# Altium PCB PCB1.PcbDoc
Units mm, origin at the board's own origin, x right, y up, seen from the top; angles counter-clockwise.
Board outline 106 x 54 mm, 2 copper layers (Top Layer, Bottom Layer), stack 1.571 mm thick; 62 components, 67 nets, 276 pads, 44 vias.
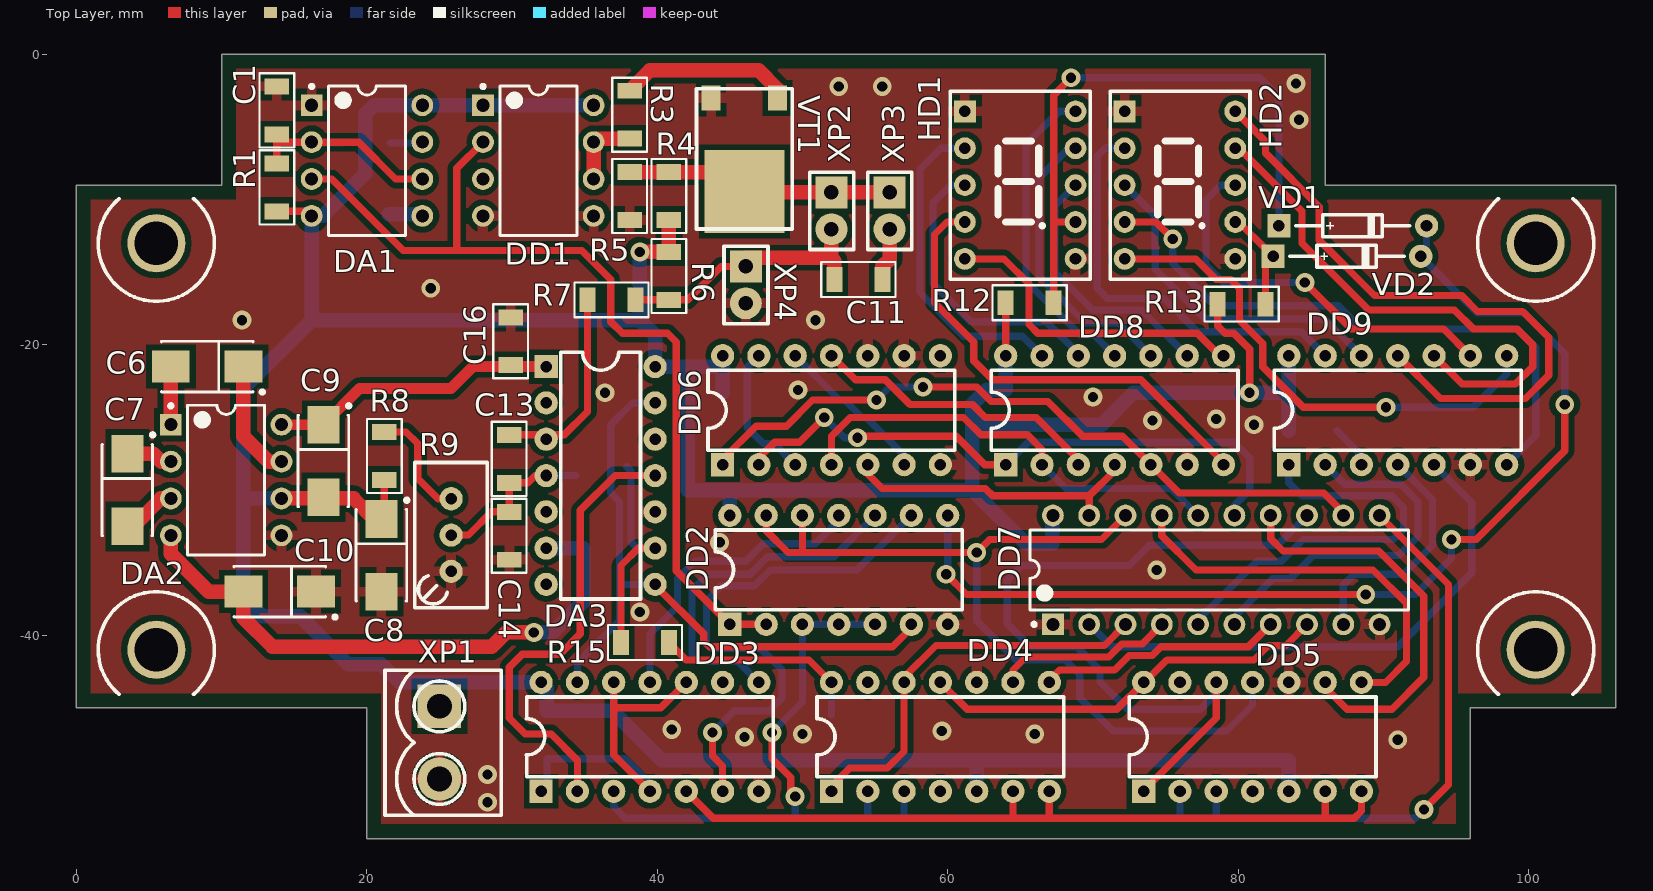
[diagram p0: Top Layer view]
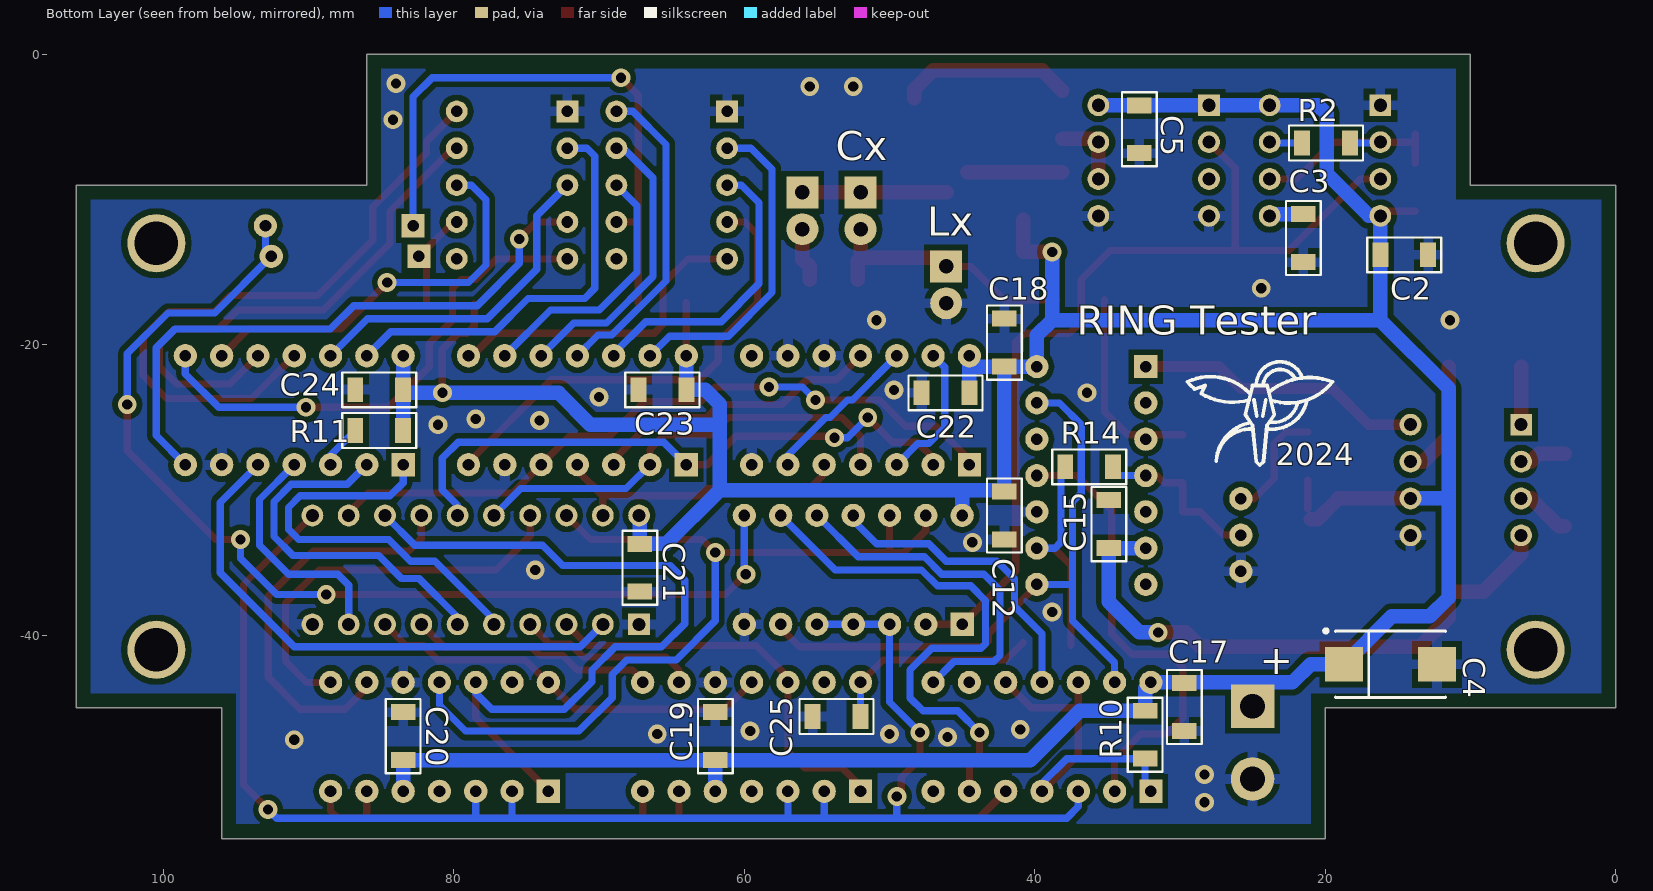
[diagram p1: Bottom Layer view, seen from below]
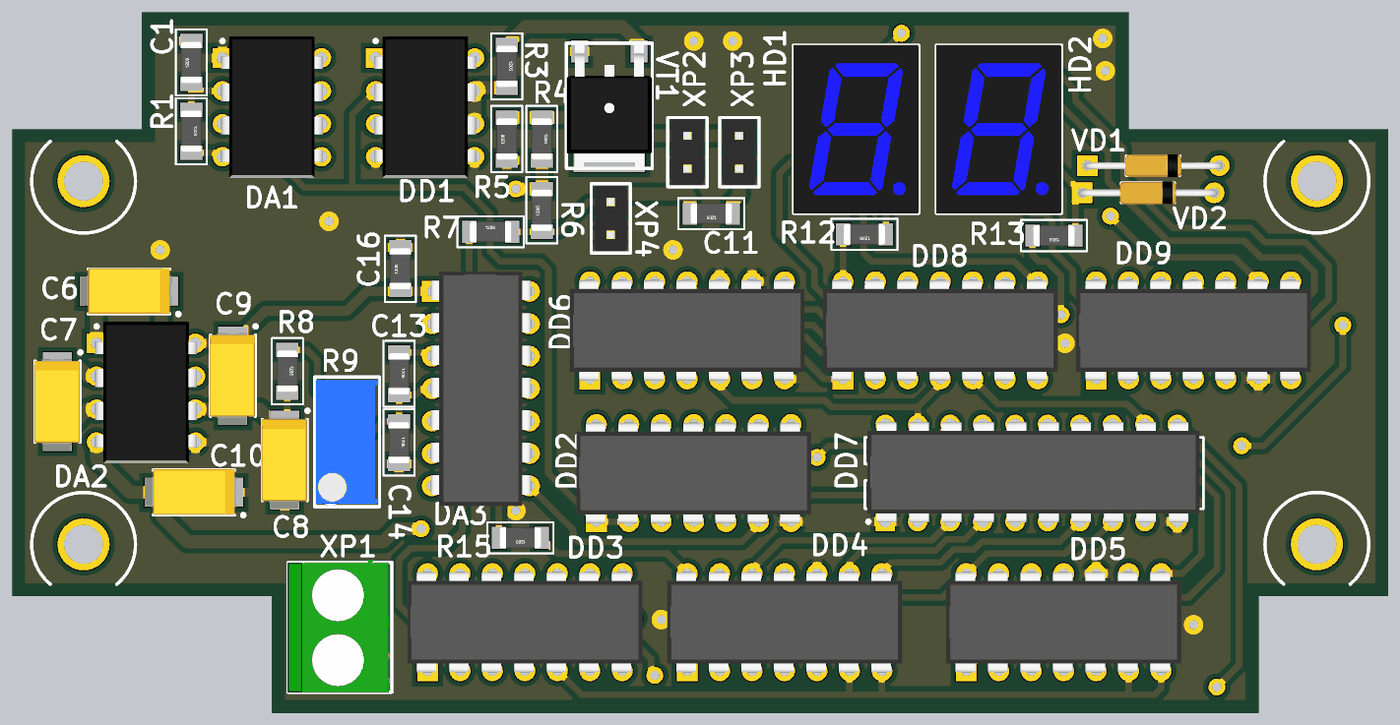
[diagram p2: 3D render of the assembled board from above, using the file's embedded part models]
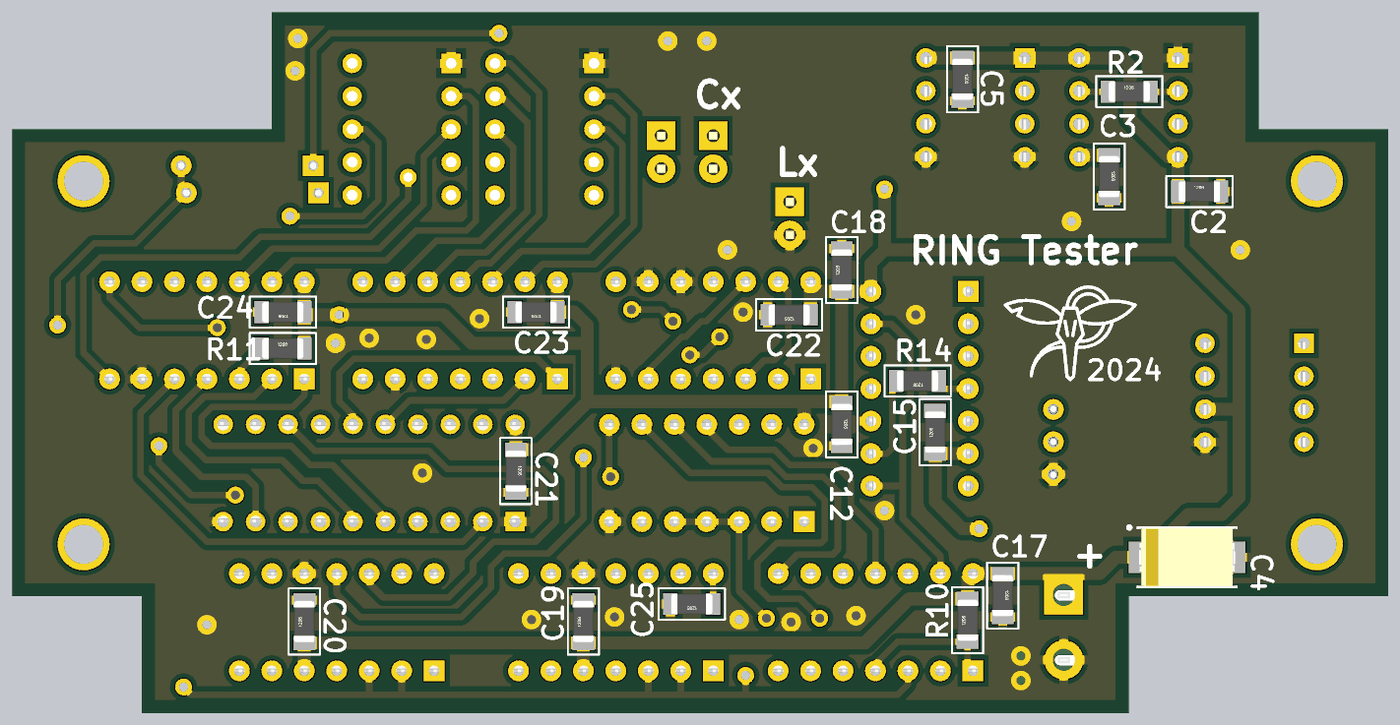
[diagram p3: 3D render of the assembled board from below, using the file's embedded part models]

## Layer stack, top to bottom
Top Layer: signal copper 0.0356
Dielectric: core 1.5, FR-4, Dk 4.8
Bottom Layer: signal copper 0.0356

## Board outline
0,-45 0,-9 10,-9 10,0 86,0 86,-9 106,-9 106,-45 96,-45 96,-54 20,-54 20,-45

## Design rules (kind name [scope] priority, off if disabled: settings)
Clearance Clearance_poly [InPolygon] p1: gap=0.4
Clearance [All] p2: gap=0.2
ComponentClearance [All] p1: gap=0.25 collisioncheckmode=3 verticalgap=0.25 showdistances=FALSE
Height [All] p1: minheight=0 maxheight=45 prefheight=12.7
PolygonConnect [All] p1: connectstyle=Relief reliefconductorwidth=0.7 reliefentries=4 polygonreliefangle="90 Angle"
RoomDefinition Sch1 [InComponentClass('Sch1')] p1: confinementstyle=ConfineIn formatcopy=TRUE lockcomponents=FALSE outline 0,-54 106,-54 106,0 0,0
RoutingVias [All] p1: holewidth=0.7 width=1.3 viastyle="Through Hole" minholewidth=0.5 minwidth=1 maxholewidth=1 maxwidth=1.5
SilkscreenOverComponentPads [All] p1: minsilkscreentomaskgap=0.254
SolderMaskExpansion [All] p1: expansion=0.102
Width [All] p1: maxlimit=5 minlimit=0.3 preferedwidth=0.7
25 further rules are at their usual default settings.

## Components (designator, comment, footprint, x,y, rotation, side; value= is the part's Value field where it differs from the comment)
2024 "2024" "Rat's logo" 24.5,-24.8 r180 bottom
C1 "C_1206" RC_1206 13.8,-5.5 r90 top
C2 "C_1206" RC_1206 16.2,-13.8 r180 bottom
C3 "C_1206" RC_1206 21.5,-11 r270 bottom
C4 "Type D" "Type D" 15.5,-42 r180 bottom
C5 "C_1206" RC_1206 32.8,-3.5 r270 bottom
C6 "Type C" "Type C" 9,-21.5 r180 top
C7 "Type C" "Type C" 3.5,-30 r270 top
C8 "Type C" "Type C" 21,-34.5 r270 top
C9 "Type C" "Type C" 17,-28 r270 top
C10 "Type C" "Type C" 14,-37 r180 top
C11 "C_1206" RC_1206 55.5,-15.5 r180 top
C12 "C_1206" RC_1206 42.1,-30.1 r270 bottom
C13 "C_1206" RC_1206 29.8,-26.2 r270 top
C14 "C_1206" RC_1206 29.8,-31.5 r270 top
C15 "C_1206" RC_1206 34.9,-34 r90 bottom
C16 "C_1206" RC_1206 29.9,-21.4 r90 top
C17 "C_1206" RC_1206 29.7,-43.3 r270 bottom
C18 "C_1206" RC_1206 42.1,-21.5 r90 bottom
C19 "C_1206" RC_1206 62,-48.6 r90 bottom
C20 "C_1206" RC_1206 83.5,-48.6 r90 bottom
C21 "C_1206" RC_1206 67.2,-33.7 r270 bottom
C22 "C_1206" RC_1206 44.5,-23.3 r0 bottom
C23 "C_1206" RC_1206 64,-23.1 r0 bottom
C24 "C_1206" RC_1206 83.5,-23.1 r0 bottom
C25 "C_1206" RC_1206 52,-45.6 r0 bottom
DA1 "NE555" DIP-8 16.2,-3.5 r0 top
DA2 "MAX680" DIP-8 6.5,-25.5 r0 top
DA3 "К554СА4" DIP-14-RU 36.1,-29 r0 top
DD1 "TC4420" DIP-8 28,-3.5 r0 top
DD2 "К1533ЛА3" DIP-14-RU 52.5,-35.5 r90 top
DD3 "КР1533ТМ2" DIP-14-RU 39.5,-47 r90 top
DD4 "КР1533ИЕ2" DIP-14-RU 59.5,-47 r90 top
DD5 "КР1533ИЕ2" DIP-14-RU 81,-47 r90 top
DD6 "К1533ЛЛ1" DIP-14-RU 52,-24.5 r90 top
DD7 "КР1533ИР23" DIP-20-RU 78.5,-35.5 r90 top
DD8 "КР514ИД1" DIP-14-RU 71.5,-24.5 r90 top
DD9 "КР514ИД1" DIP-14-RU 91,-24.5 r90 top
HD1 "HDSP-F513" HDSP-F 65,-9 r0 top
HD2 "HDSP-F513" HDSP-F 76,-9 r0 top
R1 "R_1206" RC_1206 13.8,-7.5 r270 top
R2 "R_1206" RC_1206 21.6,-6.1 r180 bottom
R3 "R_1206" RC_1206 38.1,-2.5 r270 top
R4 "R_1206" RC_1206 40.8,-8.1 r270 top
R5 "R_1206" RC_1206 38.1,-11.4 r90 top
R6 "R_1206" RC_1206 40.8,-16.9 r90 top
R7 "R_1206" RC_1206 35.2,-16.9 r0 top
R8 "R_1206" RC_1206 21.2,-26 r270 top
R9 "3296" 3296W 25.8,-35.6 r90 top
R10 "R_1206" RC_1206 32.4,-48.5 r90 bottom
R11 "R_1206" RC_1206 86.8,-25.9 r180 bottom
R12 "R_1206" RC_1206 67.3,-17.1 r180 top
R13 "R_1206" RC_1206 81.9,-17.2 r180 top
R14 "R_1206" RC_1206 34.6,-28.4 r0 bottom
R15 "R_1206" RC_1206 40.8,-40.5 r180 top
VD1 "КД522" DO-35 87.9,-11.8 r0 top
VD2 "КД522" DO-35 87.5,-13.9 r0 top
VT1 "30N03A" TO-252 46,-3 r180 top
XP1 "Power" 2EDGV-2P 25,-44.9 r270 top
XP2 "Cap" PLS-2 52,-9.5 r270 top
XP3 "Sw" PLS-2 56,-9.5 r270 top
XP4 "Ind" PLS-2 46.1,-14.6 r270 top

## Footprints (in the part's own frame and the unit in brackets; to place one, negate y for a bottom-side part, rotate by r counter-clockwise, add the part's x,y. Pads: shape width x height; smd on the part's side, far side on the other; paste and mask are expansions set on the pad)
2EDGV-2P [mm]
  rect 3x3 hole 1.7: 1(0,0)
  round 3 hole 1.7: 2(5,0)
  silkscreen extent -2.5,-3.75 7.5,4.25, body extent -2.72,-3.8 7.52,4, height 10.22
3296W [mm]
  round 1.6 hole 0.8: 1(0,0) 2(2.5,0) 3(5,0)
  silkscreen extent -2.5,-2.5 7.5,2.5, body extent -2.26,-2.42 7.27,2.41, height 11.55
DIP-8 [mm] "DIP; 8 Leads; Row Spacing 7.62 mm; Pitch 2.54 mm"
  rect 1.5x1.5 hole 0.9: 1(0,0)
  round 1.5 hole 0.9: 2(0,-2.54) 3(0,-5.08) 4(0,-7.62) 5(7.62,-7.62) 6(7.62,-5.08) 7(7.62,-2.54) 8(7.62,0)
  silkscreen extent -0.12,-8.96 6.46,1.42, body extent -0.12,-9.27 7.75,1.65, height 5.08
DIP-14-RU [mm]
  rect 1.6x1.6 hole 0.8: 1(-3.75,7.5)
  round 1.6 hole 0.8: 2(-3.75,5) 3(-3.75,2.5) 4(-3.75,0) 5(-3.75,-2.5) 6(-3.75,-5) 7(-3.75,-7.5) 8(3.75,-7.5) 9(3.75,-5) 10(3.75,-2.5) 11(3.75,0) 12(3.75,2.5) 13(3.75,5) 14(3.75,7.5)
  silkscreen extent -2.75,-8.5 2.75,8.5, body extent -3.88,-9.05 3.88,9.05, height 4.5
DIP-20-RU [mm]
  rect 1.5x1.5 hole 0.9: 1(-3.75,11.25)
  round 1.5 hole 0.9: 2(-3.75,8.75) 3(-3.75,6.25) 4(-3.75,3.75) 5(-3.75,1.25) 6(-3.75,-1.25) 7(-3.75,-3.75) 8(-3.75,-6.25) 9(-3.75,-8.75) 10(-3.75,-11.25) 11(3.75,-11.25) 12(3.75,-8.75) 13(3.75,-6.25) 14(3.75,-3.75) 15(3.75,-1.25) 16(3.75,1.25) 17(3.75,3.75) 18(3.75,6.25) 19(3.75,8.75) 20(3.75,11.25)
  silkscreen extent -3.87,-13.25 2.75,12.82, body extent -3.82,-12.98 3.94,12.62, height 4.5
DO-35 [mm]
  rect 1.6x1.6 hole 0.8: 1(-5.084,0)
  round 1.6 hole 0.8: 2(5.084,0)
  silkscreen extent -3.94,-0.75 3.94,0.75, body extent -5.35,-0.89 5.34,0.86, height 2.15
HDSP-F [mm]
  rect 1.5x1.5 hole 0.8: 1(-3.81,5.08)
  round 1.5 hole 0.8: 2(-3.81,2.54) 3(-3.81,0) 4(-3.81,-2.54) 5(-3.81,-5.08) 6(3.81,-5.08) 7(3.81,-2.54) 8(3.81,0) 9(3.81,2.54) 10(3.81,5.08)
  silkscreen extent -4.81,-6.48 4.83,6.48, body extent -4.8,-6.5 4.8,6.5, height 7
PLS-2 [mm]
  rect 2.2x2.2 hole 1: 1(0,0)
  round 2.2 hole 1: 2(2.54,0)
  silkscreen extent -1.4,-1.5 3.94,1.52, body extent -1.27,-1.27 3.81,1.27, height 8.54
"Rat's logo" [mm]
  silkscreen extent -5,-3.5 5,3.64
RC_1206 [mm]
  rect 1.1x1.7 smd: 1(0,0) 2(3.3,0)
  silkscreen extent -0.9,-1.2 4.2,1.2, body extent 0.05,-0.8 3.25,0.8, height 1
TO-252 [mm]
  rect 1.3x1.7 smd: 1(-2.285,0) 3(2.285,0)
  rect 5.5x5.7 smd: 2(0,6.44)
  silkscreen extent -3.3,-0.64 3.3,9.02, body extent -3.29,-0.65 3.29,9.05, height 2.3
"Type C" [mm]
  rect 2.6x2.2 smd: 1(-2.5,0) 2(2.5,0)
  silkscreen extent -3.93,-1.75 3.15,1.87, body extent -3.8,-1.8 3.8,1.71, height 2.79
"Type D" [mm]
  rect 2.6x2.4 smd: 1(-3.2,0) 2(3.2,0)
  silkscreen extent -4.58,-2.3 3.8,2.42, body extent -3.7,-2.22 3.7,2.23, height 3

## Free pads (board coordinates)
  round 4 hole 3: 0(5.5,-41) 0(5.5,-13) 0(100.5,-41) 0(100.5,-13)

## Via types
v1: diameter 1.3, hole 0.7, Top Layer to Bottom Layer, 44 vias

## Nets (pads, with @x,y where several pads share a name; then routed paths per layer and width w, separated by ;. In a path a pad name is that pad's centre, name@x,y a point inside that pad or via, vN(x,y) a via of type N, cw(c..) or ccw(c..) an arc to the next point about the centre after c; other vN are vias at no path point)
GND: C1.2 C2.2 C3.2 C4.2 C5.2 C8.2 C10.1 C12.2 C14.2 C15.2 C16.2 C17.2 C18.2 C19.2 C20.2 C21.2 C22.2 C23.2 C24.2 C25.2 DA1.1 DA2.5 DA3.10 DD1.4 DD1.5 DD2.7 DD3.7 DD4.10 DD5.10 DD6.7 DD6.9 DD6.10 DD7.1 DD7.10 DD8.6 DD9.6 HD1.1 HD1.6 HD2.1 HD2.6 R5.1 R9.1 VT1.3 XP1.2 XP4.2
  other v1: 28.3,-51.5 28.3,-49.6 91,-47.2 46,-47 50,-46.8 66,-46.8 59.6,-46.6 41,-46.5 38.8,-38.4 74.4,-35.5 44.3,-33.6 81.1,-25.5 74.1,-25.2 78.5,-25.1 70,-23.6 36.4,-23.3 49.7,-23.1 11.4,-18.3 50.9,-18.3 24.4,-16.1 84.2,-4.5 52.5,-2.2 55.5,-2.2 84,-2
NetC1_1: C1.1 DA1.2 DA1.6 R1.1 R2.2 | length 15.1
  Top Layer w0.5: R1.1 C1.1 ; C1.1@13.86,-6.04 DA1.2 19.44,-6.04 21.98,-8.58 DA1.6
  Bottom Layer w0.5: DA1.2@16.26,-6.1 R2.2
NetC3_1: C3.1 DA1.5 | length 2.2
  Bottom Layer w1: C3.1 DA1.5@23.7,-11
NetC6_1: C6.1 DA2.7 | length 8.1
  Top Layer w1: C6.1 11.5,-26.3 13.24,-28.04 DA2.7
NetC6_2: C6.2 DA2.1 | length 4
  Top Layer w1: DA2.1 C6.2
NetC7_1: C7.1 DA2.2 | length 3.2
  Top Layer w1: C7.1 5.3,-27.5 5.84,-28.04 DA2.2
NetC7_2: C7.2 DA2.3 | length 3.8
  Top Layer w1: C7.2 3.9,-32.5 5.82,-30.58 DA2.3
NetC11_1: C11.1 XP3.2 | length 3.7
  Top Layer w1: C11.1 55.5,-14.6 56,-14.1 XP3.2
NetC11_2: C11.2 R6.1 R7.2 XP2.2 XP4.1 | length 18
  Top Layer w0.5: R7.2 R6.1 42.1,-16.9 44.4,-14.6 XP4.1
  Top Layer w1: XP4.1@46.1,-14 52,-14 ; XP2.2 52,-14 ; C11.2 52.2,-14.2 52,-14
NetC13_1: C13.1 DA3.3 R7.1 | length 13.8
  Top Layer w0.5: C13.1 33.6,-26.2 35.2,-24.6 R7.1
NetC13_2: C13.2 C14.1 DA3.4 R9.2 R14.1 | length 11.5
  Top Layer w0.5: R9.2 27,-33.1 28.6,-31.5 C14.1 C13.2 31.1,-29.5 31.6,-29 DA3.4
  Bottom Layer w0.5: DA3.4 R14.1@34.4,-29
NetC25_1: C25.1 DD4.14 R15.1 | length 14.6
  Top Layer w0.5: R15.1 42,-41.7 50.45,-41.7 DD4.14
  Bottom Layer w0.5: C25.1@52,-45.5 DD4.14
NetDA1_3: DA1.3 DD1.2 DD2.1 DD2.2 | length 63.1
  Top Layer w0.5: DA1.3 17.58,-8.58 22.5,-13.5 26.2,-13.5 ; DD1.2 26.2,-7.84 26.2,-13.5 ; DD2.2 DD2.1 41.3,-35.55 41.3,-19.8 40.7,-19.2 37.6,-19.2 36.8,-18.4 36.8,-15.5 34.8,-13.5 26.2,-13.5
NetDA1_7: DA1.7 R2.1 | length 2.2
  Bottom Layer w0.5: R2.1 DA1.7@23.76,-6.1
NetDA3_8: DA3.8 DA3.13 DD2.6 DD3.13 | length 45.8
  Top Layer w0.5: DA3.8 39.85,-36.55 43.2,-39.9 43.2,-40.4 43.6,-40.8 56.2,-40.8 57.5,-39.5 DD2.6
  Bottom Layer w0.5: DD3.13 34.5,-41.9 37.4,-39 37.4,-36.6 ; DA3.8 37.4,-36.5 37.4,-30.8 36.8,-30.2 36.8,-25.5 38.3,-24 DA3.13
NetDA3_9: DA3.9 R14.2 R15.2 | length 15.5
  Top Layer w0.5: R15.2@37.5,-40.7 37.5,-35.2 38.7,-34 DA3.9
  Bottom Layer w0.5: R14.2 38.2,-28.7 38.2,-33.6 38.6,-34 DA3.9
NetDA3_11: DA3.11 DD3.2 | length 32
  Top Layer w0.5: DD3.2 34.5,-48.6 32.7,-46.8 30.9,-46.8 29.8,-45.7 29.8,-42.2 30.7,-41.3 33.3,-41.3 34.7,-39.9 34.7,-31.4 37.1,-29 DA3.11
NetDD1_6: DD1.6 DD1.7 R3.2 | length 5.1
  Top Layer w1: DD1.6 DD1.7 35.86,-5.8 R3.2
NetDD2_3: DD2.3 DD2.4 DD2.5 DD3.3 DD4.2 DD4.3 DD5.2 DD5.3 DD7.11 | length 107.5
  Top Layer w0.5: v1(47.9,-46.7) 47.9,-48.5 49.2,-49.8 49.2,-50.8 v1(49.5,-51.1) ; DD7.11 94.5,-36.5 94.5,-50.3 v1(92.8,-52)
  Bottom Layer w0.5: DD3.3 37,-51.8 37.8,-52.6 49.5,-52.6 ; v1(47.9,-46.7) 50,-44.6 DD2.3 DD2.4 DD2.5 ; v1(49.5,-51.1) 49.5,-52.6 ; DD4.2 54.5,-52.6 ; DD4.3 57,-52.6 ; 76,-52.5 DD5.2 ; DD5.3 78.5,-52.6 ; v1(92.8,-52) 92.2,-52.6 78.5,-52.6 ; 49.5,-52.6 54.5,-52.6 ; 54.5,-52.6 57,-52.6 ; 57,-52.6 78.5,-52.6
NetDD2_8: DD2.8 VD1.2 VD2.2 | length 73.8
  Top Layer w0.5: v1(59.9,-35.8) 61.3,-37.2 v1(88.8,-37.2) ; v1(94.7,-33.4) 96.4,-33.4 102.5,-27.3 v1(102.5,-24.1)
  Bottom Layer w0.5: v1(59.9,-35.8) 60,-35.7 DD2.8 ; v1(88.8,-37.2) 92.2,-37.2 94.7,-34.7 v1(94.7,-33.4) ; VD1.2 92.983,-13.5 VD2.2 96.484,-17.8 99.7,-17.8 102.5,-20.6 v1(102.5,-24.1)
NetDD2_9: DD2.9 DD3.6 | length 37.5
  Top Layer w0.5: v1(43.8,-46.7) 43.8,-48.3 44.5,-49 DD3.6
  Bottom Layer w0.5: v1(43.8,-46.7) 45.3,-45.2 47.7,-45.2 48.6,-44.3 48.6,-42.4 47.1,-40.9 43.7,-40.9 43.4,-40.6 43.4,-37.6 44.4,-36.6 46.7,-36.6 47.8,-35.5 53.75,-35.5 DD2.9
NetDD2_10: DD2.10 DD3.8 | length 24.6
  Bottom Layer w0.5: DD3.8 45.55,-41.8 42.8,-41.8 42.4,-41.4 42.4,-36.9 43.5,-35.8 46.4,-35.8 47.6,-34.6 52.15,-34.6 DD2.10
NetDD2_11: DD2.11 DD3.11 | length 21
  Bottom Layer w0.5: DD3.11 39.5,-39.9 41.4,-38 41.4,-36.1 42.6,-34.9 46.1,-34.9 47.3,-33.7 50.9,-33.7 52.5,-32.1 DD2.11
NetDD2_12: DD2.12 DD2.13 DD5.11 DD7.18 | length 60.1
  Top Layer w0.5: DD2.13 47.5,-32.8 49,-34.3 50,-34.3 ; DD2.12 50,-34.3 ; DD7.18 70.6,-33.4 62.9,-33.4 v1(62,-34.3) 50,-34.3
  Bottom Layer w0.5: v1(62,-34.3) 62,-39 64.7,-41.7 68.1,-41.7 69.1,-42.7 69.1,-44.3 71.4,-46.6 79.2,-46.6 81,-44.8 DD5.11
NetDD3_1: DD3.1 DD3.4 DD3.10 DD3.12 R10.1 | length 24.8
  Top Layer w0.5: DD3.12 37,-45 ; DD3.4 37,-48.25 37,-45 ; DD3.10 40.25,-45 37,-45
  Bottom Layer w0.5: DD3.1@32.4,-50.35 R10.1 37.8,-48.5 39.5,-50.2 DD3.4 ; DD3.10@42,-43.6 DD3.10
NetDD3_5: DD3.5 DD4.6 DD4.7 DD5.6 DD5.7 | length 54.4
  Top Layer w0.5: DD3.5 43.85,-52.6 64.5,-52.6 ; DD4.6 64.5,-52.6 ; DD4.7 67,-52.6 ; DD5.6 86,-52.6 ; DD5.7 88.5,-52.1 88,-52.6 86,-52.6 ; 64.5,-52.6 67,-52.6 ; 67,-52.6 86,-52.6
NetDD4_1: DD4.1 DD4.12 DD7.3 | length 28.2
  Top Layer w0.5: DD4.1 52,-50.4 53.25,-49.15 55.85,-49.15 57,-48 DD4.12 57,-42.9 59.2,-40.7 70.8,-40.7 DD7.3
NetDD4_8: DD4.8 DD7.7 | length 17
  Top Layer w0.5: DD4.8 67,-43.1 67.7,-42.4 71.5,-42.4 72.5,-41.4 74.1,-41.4 74.7,-40.8 80.7,-40.8 DD7.7
NetDD4_9: DD4.9 DD7.4 | length 12.4
  Top Layer w0.5: DD4.9 64.5,-42.4 65.4,-41.5 71.1,-41.5 72,-40.6 73.4,-40.6 DD7.4
NetDD4_11: DD4.11 DD5.14 DD7.8 | length 28.4
  Top Layer w0.5: DD4.11 61.35,-45.1 71.65,-45.1 DD5.14 73.55,-43.25 75.1,-41.7 81.1,-41.7 82.1,-40.7 83.3,-40.7 DD7.8
NetDD5_1: DD5.1 DD5.12 DD7.13 | length 53.6
  Top Layer w0.5: DD5.1 73.5,-50.7 78.5,-45.7 DD5.12
  Bottom Layer w0.5: DD5.12 78.5,-44 77.4,-45.1 72.4,-45.1 70.5,-43.2 70.5,-42.4 68.9,-40.8 65.7,-40.8 64.1,-39.2 64.1,-36.2 65.1,-35.2 72.5,-35.2 73.9,-33.8 82.7,-33.8 DD7.13
NetDD5_8: DD5.8 DD7.17 | length 27.9
  Top Layer w0.5: DD7.17 74.75,-33.15 77.1,-35.5 89.3,-35.5 91.6,-37.8 91.6,-41.8 90.15,-43.25 DD5.8
NetDD5_9: DD5.9 DD7.14 | length 28.1
  Top Layer w0.5: DD7.14 82.25,-33.35 83.1,-34.2 89.7,-34.2 92.8,-37.3 92.8,-42.9 90.6,-45.1 87.5,-45.1 86,-43.6 DD5.9
NetDD6_1: DD6.1 DD7.12 DD8.5 | length 49
  Top Layer w0.5: DD6.1 44.5,-27.9 46.8,-25.6 48.9,-25.6 50.7,-23.8 v1(55.1,-23.8) ; v1(58.3,-22.9) 62,-22.9 63,-23.9 66.9,-23.9 69.3,-26.3 72.05,-26.3 DD8.5 75.95,-30.2 85.9,-30.2 87.25,-31.55 DD7.12
  Bottom Layer w0.5: v1(55.1,-23.8) 56,-22.9 v1(58.3,-22.9)
NetDD6_2: DD6.2 DD7.15 DD8.1 | length 42.3
  Top Layer w0.5: DD6.2 47,-27.8 48.1,-26.7 49.8,-26.7 v1(51.5,-25) ; v1@54,-26.3 60.6,-26.3 62.55,-28.25 DD8.1
  Bottom Layer w0.5: v1(51.5,-25) 52.9,-26.4 v1(53.8,-26.4) ; DD8.1@64,-28.5 DD8.1 65.55,-26.7 79.7,-26.7 80.8,-27.8 80.8,-30 79.75,-31.05 DD7.15
NetDD6_3: DD6.3 DD6.13 | length 9.6
  Bottom Layer w0.5: DD6.13 46.2,-21.55 46.2,-25.7 47.3,-26.8 48.05,-26.8 DD6.3
NetDD6_4: DD6.4 DD7.16 DD8.2 | length 31.1
  Top Layer w0.5: DD6.4 52,-26.3 53.3,-25 61.1,-25 62.3,-26.2 65.5,-26.2 66.5,-27.2 DD8.2
  Bottom Layer w0.5: DD8.2 68.15,-29.9 75.4,-29.9 DD7.16
NetDD6_5: DD6.5 DD7.19 DD8.4 | length 20.7
  Top Layer w0.5: DD6.5 54.5,-28.9 55.5,-29.9 62.6,-29.9 63.1,-30.4 69.75,-30.4 ; DD7.19 69.75,-30.4 ; DD8.4 71.5,-28.65 69.75,-30.4
NetDD6_6: DD6.6 DD6.12 | length 11
  Bottom Layer w0.5: DD6.12 52.55,-23.8 52.9,-23.8 54.1,-25 54.4,-25 57,-27.6 DD6.6
NetDD6_11: DD6.11 DD8.3 | length 20.3
  Top Layer w0.5: DD6.11 53.65,-22.4 55.7,-22.4 57.4,-24.1 61.7,-24.1 62.6,-25 66.1,-25 69,-27.9 DD8.3
NetDD7_2: DD7.2 DD9.5 | length 37.6
  Bottom Layer w0.5: DD7.2 71.3,-40.8 91,-40.8 96.1,-35.7 96.1,-30.85 DD9.5
NetDD7_5: DD7.5 DD9.1 | length 28.4
  Bottom Layer w0.5: DD7.5 77.25,-38.95 81.3,-34.9 83,-34.9 84.5,-33.4 90.7,-33.4 91.4,-32.7 91.4,-31.2 90.6,-30.4 84.4,-30.4 83.5,-29.5 DD9.1
NetDD7_6: DD7.6 DD9.2 | length 25.3
  Bottom Layer w0.5: DD7.6 79.75,-38.75 82.4,-36.1 83.6,-36.1 85.2,-34.5 91.1,-34.5 92.4,-33.2 92.4,-30.8 91.2,-29.6 87.35,-29.6 DD9.2
NetDD7_9: DD7.9 DD9.4 | length 17.1
  Bottom Layer w0.5: DD7.9 87.65,-39.25 87.25,-38.85 87.25,-36.55 88,-35.8 91.4,-35.8 93.4,-33.8 93.4,-30.65 DD9.4
NetDD8_7: DD8.7 HD1.4 | length 32.5
  Top Layer w0.5: HD1.4 59.96,-11.54 59.1,-12.4 59.1,-17.1 61.8,-19.8 61.8,-21.1 63.1,-22.4 73.3,-22.4 79,-28.1 DD8.7
NetDD8_8: DD8.8 HD1.5 | length 22.2
  Top Layer w0.5: HD1.5 63.88,-14.08 65.6,-15.8 65.6,-18.6 66.2,-19.2 77.2,-19.2 78.75,-20.75 DD8.8
NetDD8_9: DD8.9 HD1.8 | length 18.1
  Bottom Layer w0.5: HD1.8 67.4,-10.41 67.4,-15 70,-17.6 73.35,-17.6 DD8.9
NetDD8_10: DD8.10 HD1.9 | length 20.1
  Bottom Layer w0.5: HD1.9 68.34,-6.46 66.3,-8.5 66.3,-15.3 69.5,-18.5 71.75,-18.5 DD8.10
NetDD8_11: DD8.11 HD1.10 | length 22
  Bottom Layer w0.5: HD1.10 67.68,-3.92 65.4,-6.2 65.4,-15.6 69.125,-19.325 70.075,-19.325 DD8.11
NetDD8_12: DD8.12 HD1.3 | length 20.4
  Bottom Layer w0.5: HD1.3 60.2,-9 59,-10.2 59,-15.8 61.6,-18.4 66.8,-18.4 69,-20.6 DD8.12
NetDD8_13: DD8.13 HD1.2 | length 22.4
  Bottom Layer w0.5: HD1.2 59.54,-6.46 58.1,-7.9 58.1,-16.4 61.1,-19.4 65.15,-19.4 DD8.13
NetDD9_3: DD9.3 R11.1 | length 3.1
  Bottom Layer w0.5: R11.1 88.5,-27.6 DD9.3
NetDD9_7: DD9.7 HD2.4 | length 41.8
  Top Layer w0.5: HD2.4 74.34,-11.54 v1(75.5,-12.7)
  Bottom Layer w0.5: v1(75.5,-12.7) 75.5,-14.4 78.4,-17.3 86.9,-17.3 88.5,-18.9 99.2,-18.9 100.5,-20.2 100.5,-26.25 DD9.7
NetDD9_8: DD9.8 HD2.5 | length 35
  Top Layer w0.5: HD2.5 77.08,-14.08 78.5,-15.5 79.5,-15.5 80.1,-16.1 80.1,-18.3 81.7,-19.9 81.7,-21.5 84.5,-24.3 v1(90.2,-24.3)
  Bottom Layer w0.5: v1(90.2,-24.3) 96.2,-24.3 98.5,-22 DD9.8
NetDD9_9: DD9.9 HD2.8 | length 27.7
  Top Layer w0.5: v1(84.6,-15.7) 87.8,-18.9 94.15,-18.9 DD9.9
  Bottom Layer w0.5: HD2.8 78.8,-9 77.8,-10 77.8,-14.5 79,-15.7 v1(84.6,-15.7)
NetDD9_10: DD9.10 HD2.9 | length 37
  Top Layer w0.5: HD2.9 80.06,-6.46 84.4,-10.8 84.4,-13 89,-17.6 94.9,-17.6 96.2,-18.9 99.2,-18.9 100.3,-20 100.3,-21.5 99.1,-22.7 95.45,-22.7 DD9.10
NetDD9_11: DD9.11 HD2.10 | length 44.7
  Top Layer w0.5: HD2.10 81.9,-6.01 81.9,-6.8 85.6,-10.5 85.6,-12.8 89.4,-16.6 95.4,-16.6 96.5,-17.7 99.6,-17.7 101.4,-19.5 101.4,-22.1 99.8,-23.7 93.95,-23.7 DD9.11
NetDD9_12: DD9.12 HD2.3 | length 23.3
  Bottom Layer w0.5: HD2.3 74.3,-11.11 74.3,-14.8 77.7,-18.2 85.95,-18.2 DD9.12
NetDD9_13: DD9.13 HD2.2 | length 28.8
  Bottom Layer w0.5: HD2.2 70.84,-6.46 70.3,-7 70.3,-16.1 71,-16.8 74.9,-16.8 77.2,-19.1 84.35,-19.1 DD9.13
NetHD1_7: HD1.7 R12.1 VD1.1 | length 41.3
  Top Layer w0.5: R12.1 67.3,-11.5 ; v1(68.5,-1.6) 67.3,-2.8 67.3,-11.5 ; HD1.7 67.34,-11.54 67.3,-11.5
  Bottom Layer w0.5: v1(68.5,-1.6) 81.5,-1.6 82.816,-2.917 VD1.1
NetHD2_7: HD2.7 R13.1 VD2.1 | length 6.5
  Top Layer w0.5: HD2.7 80.04,-11.54 81.9,-13.4 R13.1@81.9,-17
NetR3_1: R3.1 VT1.1 | length 11.9
  Top Layer w1: R3.1 39.5,-1.1 47,-1.1 48.285,-2.385 VT1.1
NetR4_1: R4.1 R5.2 VT1.2 XP2.1 XP3.1 | length 16.5
  Top Layer w1: R5.2 R4.1 VT1.2@44.66,-8.1 ; VT1.2@46.06,-9.5 XP2.1 XP3.1
NetR8_1: R8.1 R9.3 | length 7.9
  Top Layer w0.5: R8.1 22.7,-26 23.5,-26.8 23.5,-29.2 24.9,-30.6 R9.3
V+: C9.1 C16.1 DA2.8 DA3.1 | length 19.9
  Top Layer w0.75: DA2.8 C9.1 19.5,-23 25.8,-23 27.3,-21.5 DA3.1
V-: C10.2 C15.1 DA2.4 DA3.6 | length 40.9
  Top Layer w1: DA2.4 6.5,-34.4 9.1,-37 C10.2 11.5,-38.8 13.5,-40.8 28.6,-40.8 29.6,-39.8 v1(31.5,-39.8)
  Bottom Layer w1: v1(31.5,-39.8) 32.8,-39.8 34.9,-37.7 C15.1 DA3.6
VCC: C2.1 C4.1 C5.1 C8.1 C9.2 C12.1 C17.1 C18.1 C19.1 C20.1 C21.1 C22.1 C23.1 C24.1 DA1.4 DA1.8 DA2.6 DA3.14 DD1.1 DD1.8 DD2.14 DD3.14 DD4.5 DD5.5 DD6.14 DD7.20 DD8.14 DD9.14 R1.2 R4.2 R6.2 R8.2 R10.2 R11.2 R12.2 R13.2 XP1.1 | length 281.1
  Top Layer w0.5: R1.2 DA1.4@15.88,-10.8 ; C8.1@21.2,-31.3 R8.2 ; DD8.14 R12.2 ; R13.2 78.6,-18.7 79.1,-19.2 79.7,-19.2 80.8,-20.3 v1(80.8,-23.3)
  Top Layer w1: DA2.6 19.08,-30.58 20.5,-32 C8.1 ; v1(38.8,-13.6) R6.2 R4.2
  Bottom Layer w1: DA2.6 11.5,-30.58 ; XP1.1 25,-43.25 ; DD3.14 25,-43.25 ; DD3.14@32.4,-43.65 R10.2 36.9,-45.2 40.3,-48.6 C19.1 ; DD1.8 C5.1 DD1.1 DA1.8 20.5,-3.5 19.9,-4.1 19.9,-8.2 16.98,-11.12 DA1.4 C2.1 16.2,-18.3 ; v1(38.8,-13.6) 38.8,-18.3 ; DD6.14@44.4,-21.5 C18.1 ; C22.1 DD6.14 ; DD2.14 45,-30.1 ; 61.8,-25.5 70.6,-25.5 72.8,-23.3 83.3,-23.3 C24.1 ; DD4.5 C19.1 ; DD8.14 C23.1 62.7,-23.1 61.7,-24.1 61.7,-30 ; DD7.20 67.2,-31.8 C21.1 65.4,-33.7 61.7,-30 ; DD5.5 C20.1 C19.1 ; R11.2 C24.1 ; DD9.14 C24.1 ; 11.5,-30.58 11.5,-23 16.2,-18.3 ; 11.5,-30.58 11.5,-37.4 12.8,-38.7 15.4,-38.7 C4.1 21,-42 22.25,-43.25 25,-43.25 ; 16.2,-18.3 38.8,-18.3 ; 38.8,-18.3 39.85,-19.35 DA3.14 C18.1 ; C18.1 42.1,-30 61.7,-30
pads on no net: DA3.2 DA3.5 DA3.7 DA3.12 DD1.3 DD3.9 DD4.4 DD4.13 DD5.4 DD5.13 DD6.8

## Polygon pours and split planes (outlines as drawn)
GND on Bottom Layer "Bottom Layer-GND" (solid, pour order 3): 11,-1 85,-1 85,-10 105,-10 105,-44 95,-44 95,-53 21,-53 21,-44 1,-44 1,-10 11,-10
GND on Top Layer "Top Layer-GND" (solid, pour order 4): 11,-1 85,-1 85,-10 105,-10 105,-44 95,-44 95,-53 21,-53 21,-44 1,-44 1,-10 11,-10

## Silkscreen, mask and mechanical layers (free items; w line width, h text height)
Top Overlay:
  lines w0.25: 2.939,-44.073 cw(c5.5,-41) 8.061,-44.073 ; 2.939,-9.927 ccw(c5.5,-13) 8.061,-9.927 ; 97.939,-44.073 cw(c100.5,-41) 103.061,-44.073 ; 97.939,-9.927 ccw(c100.5,-13) 103.061,-9.927
Bottom Overlay:
  text "Cx" at 53.7,-7.3 h2
  text "Lx" at 47.4,-12.5 h2
  text "RING Tester" at 37.1,-19.3 h2
  text "+" at 24.5,-42.7 h2
Mechanical 32:
  the board outline again, w0.5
